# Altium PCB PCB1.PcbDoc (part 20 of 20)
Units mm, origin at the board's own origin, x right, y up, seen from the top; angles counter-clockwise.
Board outline 294.51 x 138.18 mm, 12 copper layers (Top Layer 1 _Signal, L2_GND, L3_Signals, L4_GND, L5_POWER, L6_Signals, L7_GND, L8_Signals, L9_GND, L10_POWER, L11_GND, Bottom Layer_Signals), stack 1.788 mm thick; 1254 components, 836 nets, 5699 pads, 2073 vias.
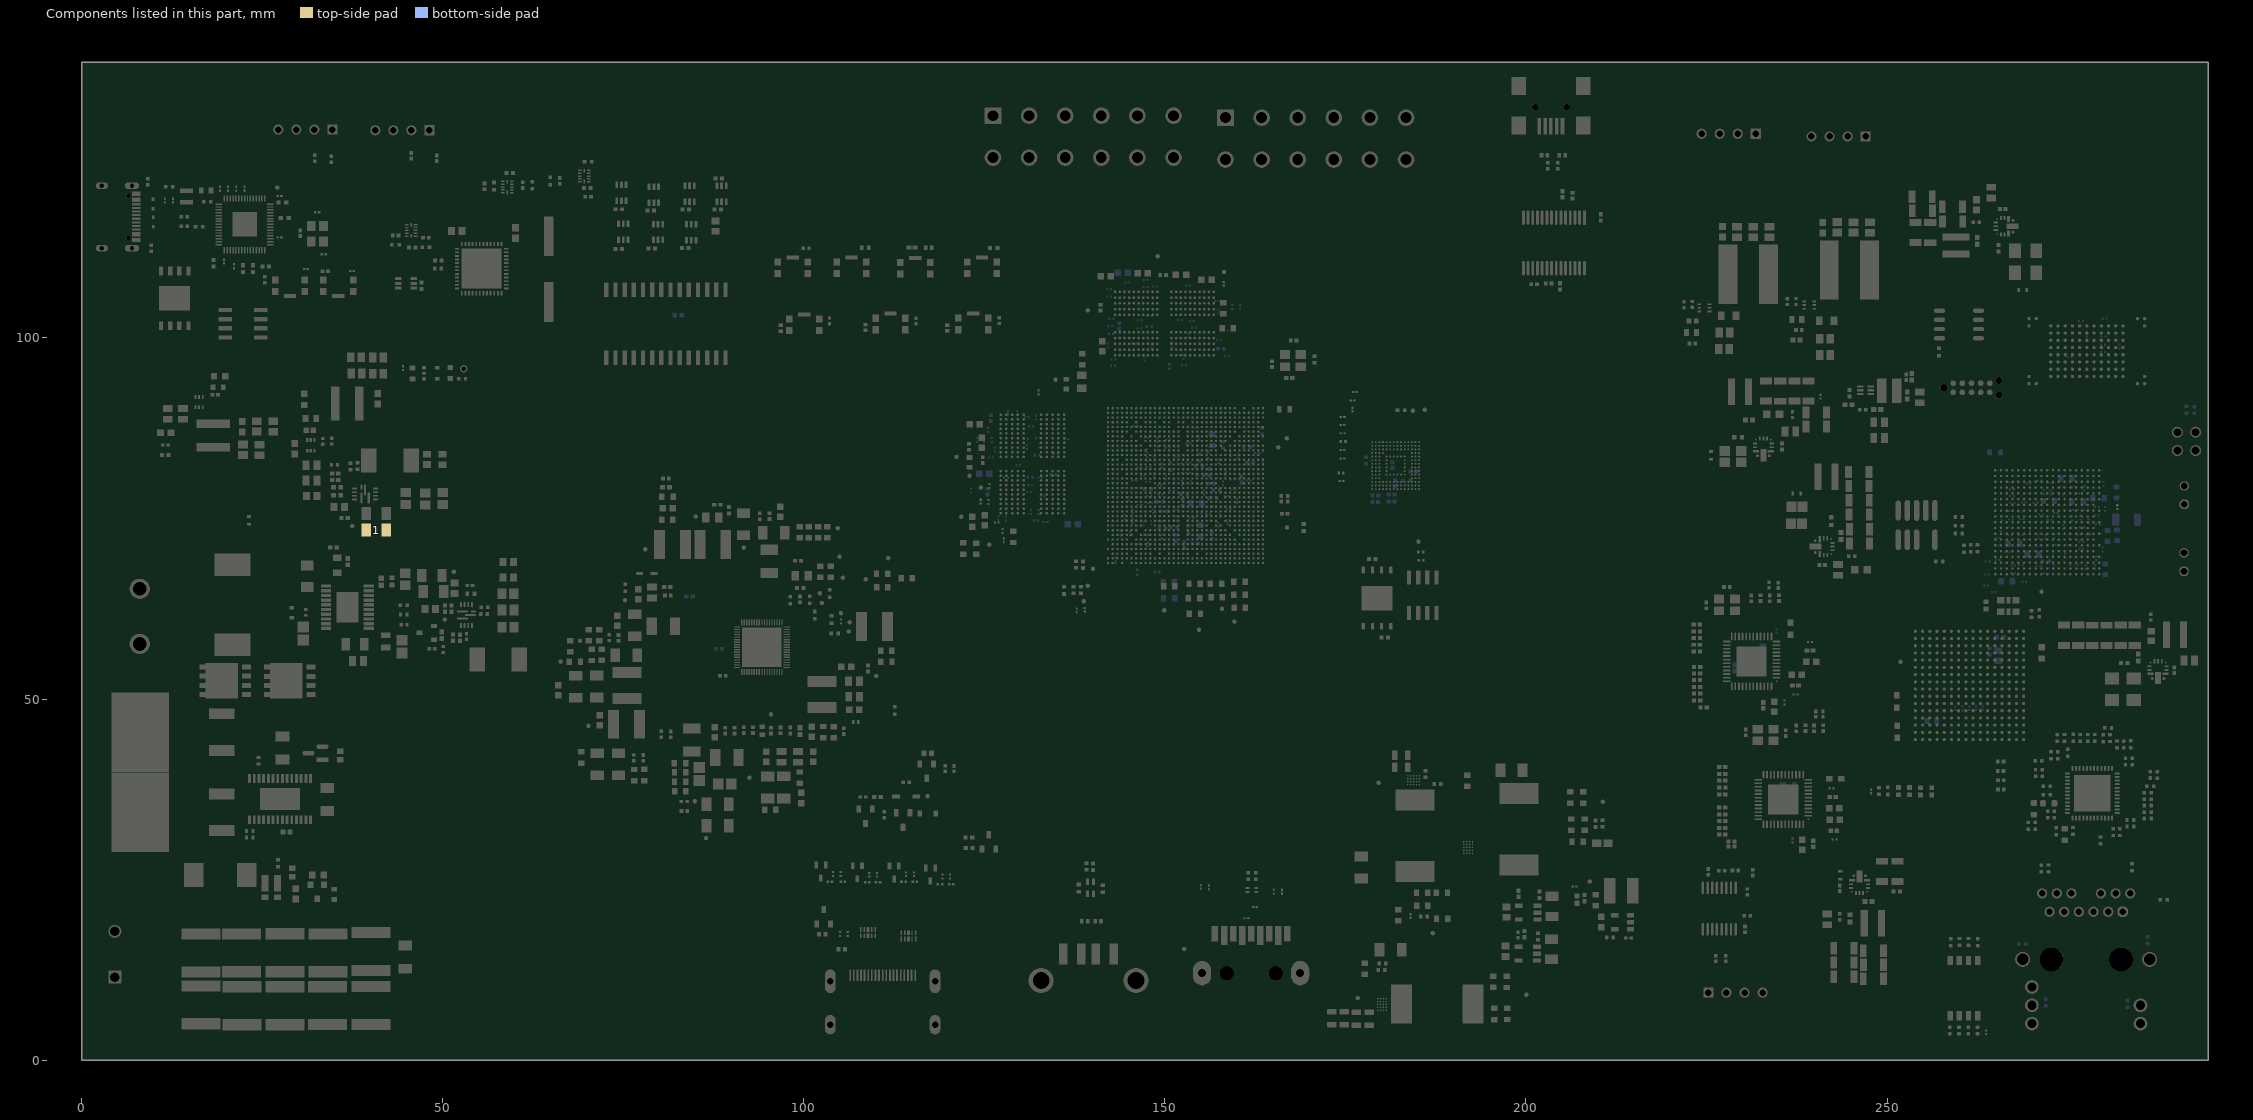
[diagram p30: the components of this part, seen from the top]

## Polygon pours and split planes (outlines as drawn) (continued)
NetC206_1 on Top Layer 1 _Signal "NONET_L04_P-001" (solid, pour order 236): 31.348,85.722 31.42,85.794 31.42,90.857 30.227,90.857 30.166,90.797 30.202,90.761 30.202,87.361 30.902,86.662 30.902,85.758
5V on Top Layer 1 _Signal "NONET_L04_P-001" (solid, pour order 235): 40.84,97.853 40.897,97.796 40.897,93.411 41.561,92.747 41.524,92.709 41.524,91.788 39.863,91.788 38.8,90.725 37.793,90.725 37.793,94.142 38.154,94.503 38.154,97.844
NetC436_1 on Top Layer 1 _Signal "NONET_L04_P-001" (solid, pour order 234): 39.424,78.502 39.431,78.509 39.431,81.181 40.533,81.181 40.91,81.559 40.91,83.091 39.678,83.091 38.8,82.213 37.822,82.213 37.822,81.282 39.085,80.019 39.085,78.502
NetR76_1 on Top Layer 1 _Signal "NONET_L04_P-001" (solid, pour order 233): 38.047,77.925 35.717,77.925 35.717,79.531 35.826,79.64 35.829,79.637 36.248,79.637 36.248,78.899 36.797,78.35 38.047,78.35
12V on Top Layer 1 _Signal "NONET_L04_P-001" (solid, pour order 226): 50.359,68 50.393,67.966 50.393,63.589 49.418,63.589 49.418,61.751 48.238,61.751 48.238,64.435 48.204,64.469 48.204,68.026
NetD13_2 on Top Layer 1 _Signal "NONET_L04_P-001" (solid, pour order 230): 13.584,31.72 18.505,31.72 18.774,31.45 18.774,21.542 13.854,21.542 13.764,21.632
NetQ18_1 on Top Layer 1 _Signal "NONET_L04_P-001" (solid, pour order 8): 31.112,53.515 34.977,53.515 34.977,49.678 31.006,49.678 31.006,53.41
3V3 on Top Layer 1 _Signal "NONET_L04_P-001" (solid, pour order 212): 69.229,121.732 69.223,121.726 67.559,121.726 67.269,121.436 64.665,121.436 64.665,121.157 64.665,120.972 67.744,120.972 68.237,121.465 69.246,121.465
3V3 on Top Layer 1 _Signal "NONET_L04_P-001" (solid, pour order 210): 19.432,115.828 19.429,115.824 16.548,115.824 16.548,115.171 19.424,115.171
3V3 on Top Layer 1 _Signal "NONET_L04_P-001" (solid, pour order 211): 20.248,118.88 20.282,118.913 20.282,120.045 22.702,120.045 22.904,120.247 22.893,120.258 22.893,120.626 19.021,120.626 19.021,119.366 19.391,118.88
RP_1V1 on Top Layer 1 _Signal "NONET_L04_P-001" (solid, pour order 214): 21.936,112.59 21.936,110.698 21.235,109.997 20.987,109.997 20.987,110.738 21.669,111.42 21.669,112.59
3V3 on Top Layer 1 _Signal "NONET_L04_P-001" (solid, pour order 213): 19.869,112.59 19.873,112.586 19.873,110.606 18.945,110.606 18.919,110.632 18.919,112.59
2V5_VSC on Top Layer 1 _Signal "NONET_L04_P-001" (solid, pour order 223): 261.779,35.623 260.256,37.145 247.439,37.145 247.439,35.623
3V3 on Top Layer 1 _Signal "NONET_L04_P-001" (solid, pour order 205): 27.339,119.866 27.4,119.805 27.4,118.476 25.832,118.476 25.832,119.866
NetR85_2 on Top Layer 1 _Signal "NONET_L04_P-001" (solid, pour order 221): 52.106,58.641 52.132,58.667 53.606,58.667 54.343,59.404 54.343,60.402 53.968,60.402 53.898,60.332 53.898,59.447 53.82,59.369 53.807,59.382 52.119,59.382
EN_MP on Top Layer 1 _Signal "NONET_L04_P-001" (solid, pour order 220): 52.7,62.852 52.598,62.75 50.048,62.75 50.048,63.245 49.985,63.307 50.644,63.307 50.794,63.457 50.786,63.464 50.786,64.712 50.951,64.877 52.457,64.877 52.716,64.618 52.716,62.845
NetC586_1 on Top Layer 1 _Signal "NONET_L04_P-001" (solid, pour order 218): 24 vertices, not listed, extent 21.582,22.115 29.454,33.911
NetC643_1 on Top Layer 1 _Signal "NONET_L04_P-001" (solid, pour order 216): 58.603,121.65 57.541,121.65 57.237,121.346 55.479,121.346 55.479,121.672 55.743,121.936 58.603,121.936
NetC542_1 on Top Layer 1 _Signal "NONET_L04_P-001" (solid, pour order 208): 19.432,118.428 17.601,118.428 17.601,120.819 17.663,120.881 18.295,120.881 18.295,119.057 18.612,118.74 19.432,118.74
+24V on Top Layer 1 _Signal "NONET_L04_P-001" (solid, pour order 204): 7.964,13.324 46.171,13.324 46.171,7.715 7.736,7.715
VCCA_1V8 on Top Layer 1 _Signal "NONET_L04_P-001" (solid, pour order 200): 45.881,112.3 47.316,112.3 47.316,114.02 47.107,114.229 45.911,114.229
VCC_5V0 on Top Layer 1 _Signal "NONET_L04_P-001" (solid, pour order 195): 40.349,78.327 50.918,78.327 50.918,82.586 45.003,82.586 42.851,80.433 42.851,79.495 42.2,78.845 40.349,78.845
VCC_1V8_S0 on Top Layer 1 _Signal "NONET_L04_P-001" (solid, pour order 26): 93.631,52.051 93.631,49.636 93.27,49.275 91.343,49.275 90.748,48.68 90.748,45.726 89.913,45.726 89.785,45.855 89.826,45.896 89.826,49.748 90.007,49.929 93.262,49.929 93.355,50.022 93.355,54.126 93.579,54.126
NetC445_1 on Top Layer 1 _Signal "NONET_L04_P-001" (solid, pour order 193): 55.521,61.956 55.521,53.9 53.798,53.9 53.733,53.965 53.733,58.469 54.757,59.493 54.757,61.013 53.709,61.013 53.709,61.851 54.691,61.851 54.927,62.087 55.505,62.087
LM_FB on Top Layer 1 _Signal "NONET_L04_P-001" (solid, pour order 32): 35.001,71.261 34.794,71.054 34.794,69.975 34.799,69.97 34.799,69.183 36.398,69.183 36.62,69.405 37.457,69.405 37.457,70.172 37.22,70.409 35.833,70.409 35.641,70.6 35.641,71.291 35.646,71.286
NetL19_1 on Top Layer 1 _Signal "NONET_L04_P-001" (solid, pour order 124): 192.073,29.176 201.522,29.176 201.858,28.839 201.858,26.599 192.969,26.599 192.047,27.522
VCC1 on Top Layer 1 _Signal "NONET_L04_P-001" (solid, pour order 117): 184.123,38.918 184.122,38.918 184.122,43.057 183.095,43.057 182.966,42.928 182.966,39.002 183.087,38.882 184.122,38.882
NetL21_1 on Top Layer 1 _Signal "NONET_L04_P-001" (solid, pour order 118): 184.145,38.706 184.157,38.695 184.157,37.674 186.053,37.674 186.098,37.629 186.098,34.469 182.765,34.469 182.72,34.514 182.799,34.593 182.799,38.729
PMIC_SW3 on Top Layer 1 _Signal "NONET_L04_P-001" (solid, pour order 18): 92.601,54.11 92.601,51.735 88.204,51.735 86.125,49.656 86.125,45.183 83.355,45.183 83.065,45.472 83.065,48.129 87.459,52.523 92.321,52.523 92.321,54.139
VDDA_1V2_S0 on Top Layer 1 _Signal "NONET_L04_P-001" (solid, pour order 25): 93.244,54.122 93.253,54.113 93.224,50.058 89.529,50.048 89.529,45.679 88.902,45.679 88.748,45.833 88.748,50.735 93.046,50.735 93.046,54.094 93.067,54.115
PMIC_PWR_CTRL2 on Top Layer 1 _Signal "NONET_L04_P-001" (solid, pour order 30): 94.681,54.04 94.681,46.558 94.721,46.519 94.623,46.421 94.623,45.699 93.745,45.699 93.53,45.914 93.53,47.683 93.762,47.916 94.373,47.916 94.373,54.017
VCC1 on Top Layer 1 _Signal "NONET_L04_P-001" (solid, pour order 34): 95.692,53.927 95.692,51.764 96.311,51.146 96.311,50.728 95.923,50.728 95.499,51.152 95.499,53.927
PMIC_FB9 on Top Layer 1 _Signal "NONET_L04_P-001" (solid, pour order 35): 96.222,54.042 96.222,52.172 97.395,50.999 97.395,46.004 97.817,45.582 99.937,45.582 99.937,46.706 98.288,48.355 98.288,50.788 96.36,52.717 96.36,54.011
PMIC_SW9 on Top Layer 1 _Signal "NONET_L04_P-001" (solid, pour order 37): 96.873,53.998 103.266,53.998 104.634,52.63 104.634,51.629 104.621,51.616 104.596,51.641 98.484,51.641 96.854,53.271 96.854,54.061 96.873,54.042
VCC1 on Top Layer 1 _Signal "NONET_L04_P-001" (solid, pour order 42): 97.397,56.394 97.44,56.352 102.477,56.352 103.19,57.064 103.173,57.081 99.95,57.081 99.501,56.632 97.338,56.632
NLDO4 on Top Layer 1 _Signal "NONET_L04_P-001" (solid, pour order 45): 97.387,57.41 97.502,57.295 99.011,57.295 101.483,59.767 104.193,59.767 104.19,61.083 102.257,61.083 98.794,57.62 97.39,57.62
NLDO3 on Top Layer 1 _Signal "NONET_L04_P-001" (solid, pour order 47): 97.243,57.718 98.808,57.718 101.933,60.842 101.933,61.394 101.043,61.394 101.043,60.754 98.323,58.034 97.249,58.034
VCC_2V0_PLDO_S3 on Top Layer 1 _Signal "NONET_L04_P-001" (solid, pour order 52): 97.369,58.385 98.176,58.385 100.221,60.431 100.221,63.706 99.091,63.706 99.091,62.823 99.091,59.632 98.139,58.681 97.375,58.681
NLDO1 on Top Layer 1 _Signal "NONET_L04_P-001" (solid, pour order 53): 97.237,58.751 98.194,58.751 99.003,59.561 99.003,63.334 98.858,63.48 97.789,63.48 97.789,62.946 98.647,62.087 98.647,59.598 98.108,59.059 97.237,59.059
PMIC_SPI_CS on Top Layer 1 _Signal "NONET_L04_P-001" (solid, pour order 54): 97.097,60.194 97.097,62.122 97.421,62.445 97.421,63.983 96.855,63.983 96.855,60.183
PMIC_SPI_CLK on Top Layer 1 _Signal "NONET_L04_P-001" (solid, pour order 55): 97.255,59.853 97.286,59.884 98.074,59.884 98.074,61.909 97.995,61.988 97.986,61.979 97.232,61.979
PMIC_INT_L on Top Layer 1 _Signal "NONET_L04_P-001" (solid, pour order 56): 96.758,60.413 96.758,64.035 97.809,65.086 99.414,65.086 99.414,65.774 97.661,65.774 96.506,64.604 96.506,60.413
VCC_1V8_S3_PLDO6 on Top Layer 1 _Signal "NONET_L04_P-001" (solid, pour order 57): 96.429,60.354 96.429,64.648 98.117,66.336 99.334,66.336 99.334,67.816 97.993,67.816 96.169,65.992 96.169,60.28 96.356,60.28
PMIC_SW4 on Top Layer 1 _Signal "NONET_L04_P-001" (solid, pour order 59): 95.414,60.472 95.414,65.721 96.574,66.882 96.574,68.168 93.866,68.168 93.911,68.122 93.911,64.993 95.049,63.855 95.049,60.418
VCCQ on Top Layer 1 _Signal "NONET_L04_P-001" (solid, pour order 61): 94.608,60.38 94.608,62.905 93.18,64.333 93.18,66.502 90.161,69.521 90.161,75.954 87.572,75.954 87.572,69.07 88.249,68.393 92.76,63.882 94.436,62.206 94.436,60.262
NetC162_1 on Top Layer 1 _Signal "NONET_L04_P-001" (solid, pour order 63): 95.479,75.426 93.305,75.426 92.491,74.613 90.534,74.613 90.534,76.532 90.572,76.57 95.491,76.57 95.491,75.846 95.504,75.833
NetC162_1 on Top Layer 1 _Signal "NONET_L04_P-001" (solid, pour order 64): 94.077,69.926 94.077,70.064 94.077,71.361 95.66,71.361 96.681,72.382 96.681,74.332 105.053,74.332 105.053,73.265 98.348,73.265 98.348,69.926
PMIC_SW10 on Top Layer 1 _Signal "NONET_L04_P-001" (solid, pour order 65): 94.293,60.289 94.352,60.289 94.352,62.12 87.008,69.464 87.008,73.867 86.727,73.894 84.755,73.894 84.755,69.213 89.598,64.37 91.31,64.37 94.122,61.558 94.122,60.289
PMIC_SW6 on Top Layer 1 _Signal "NONET_L04_P-001" (solid, pour order 67): 93.233,60.27 93.254,60.291 93.254,61.517 90.493,64.279 89.603,64.279 84.573,69.309 84.573,73.389 84.365,73.598 82.735,73.598 82.735,69.228 88.317,63.646 90.419,63.646 93.063,61.002 93.063,60.27
VOUT6 on Top Layer 1 _Signal "NONET_L04_P-001" (solid, pour order 69): 92.904,60.238 92.904,61.157 90.398,63.663 88.161,63.663 82.216,69.609 82.216,73.649 79.147,73.649 79.147,69.292 85.499,62.941 90.684,62.941 92.669,60.956 92.669,60.238
PMIC_VDC on Top Layer 1 _Signal "NONET_L04_P-001" (solid, pour order 70): 92.273,60.194 92.273,61.225 90.67,62.829 85.504,62.829 82.104,66.23 81.324,66.23 81.204,66.203 81.204,65.976 81.204,63.979 82.782,63.979 84.567,62.194 90.857,62.194 91.988,61.063 92.002,60.194
PMIC_SW2 on Top Layer 1 _Signal "NONET_L04_P-001" (solid, pour order 72): 81.407,61.248 83.28,61.248 84.379,60.149 91.201,60.149 91.285,60.065 91.285,59.511 81.481,59.511 81.439,59.553
RESET_L on Top Layer 1 _Signal "NONET_L04_P-001" (solid, pour order 75): 91.15,58.12 91.181,58.15 91.181,58.32 87.209,58.32 87.112,58.222 87.123,58.211 87.123,58.031 91.103,58.031 91.186,58.114
VCC1 on Top Layer 1 _Signal "NONET_L04_P-001" (solid, pour order 78): 91.175,57.249 91.171,57.252 88.595,57.252 88.097,56.754 88.108,56.743 91.168,56.743
PMIC_SW5 on Top Layer 1 _Signal "NONET_L04_P-001" (solid, pour order 79): 91.102,56.638 87.911,56.638 80.19,48.917 76.442,48.917 76.442,44.661 76.63,44.473 78.182,44.473 78.182,47.058 79.215,47.058 88.475,56.318 91.102,56.318
VDD_GPIO_S0 on Top Layer 1 _Signal "NONET_L04_P-001" (solid, pour order 82): 91.099,55.316 88.882,55.316 79.937,46.371 79.937,45.317 80.215,45.039 82.907,45.039 82.907,48.288 89.505,54.885 91.111,54.885
PMIC_SW1 on Top Layer 1 _Signal "NONET_L04_P-001" (solid, pour order 83): 91.15,54.792 91.147,54.789 89.35,54.789 89.35,53.582 91.186,53.582
PMIC_SW1 on Top Layer 1 _Signal "NONET_L04_P-001" (solid, pour order 86): 91.645,43.073 91.639,43.079 91.639,44.131 89.193,44.131 89.087,44.026 89.146,43.967 89.146,40.673 91.634,40.673 91.639,40.679
NetC41_1 on Top Layer 1 _Signal "NONET_L04_P-001" (solid, pour order 87): 88.508,43.1 88.497,43.089 88.497,39.91 89.047,39.36 89.047,37.369 87.089,37.369 86.671,37.787 86.671,39.6 84.737,39.6 84.405,39.932 84.405,41.593 86.353,41.593 86.902,42.142 86.902,43.111
NetC76_1 on Top Layer 1 _Signal "NONET_L04_P-001" (solid, pour order 88): 17 vertices, not listed, extent 82.868,31.486 87.393,43.417
NetC61_1 on Top Layer 1 _Signal "NONET_L04_P-001" (solid, pour order 89): 75.615,62.821 79.559,62.821 79.559,59.021 79.446,58.907 78.257,58.907 78.257,60.437 78.03,60.663 75.643,60.663
NetC61_1 on Top Layer 1 _Signal "NONET_L04_P-001" (solid, pour order 91): 74.648,55.089 74.648,58.276 74.567,58.357 72.375,58.357 72.253,58.479 72.221,58.446 69.721,58.446 69.721,56.545 69.883,56.383 72.682,56.383 73.095,55.97 73.095,55.072
VCC_2V0_PLD0_S3 on Top Layer 1 _Signal "NONET_L04_P-001" (solid, pour order 94): 65.238,51.128 72.66,51.128 72.835,50.954 72.835,48.999 65.284,48.999 65.183,49.1
VCC1 on Top Layer 1 _Signal "NONET_L04_P-001" (solid, pour order 121): 179.955,7.392 179.927,7.365 172.327,7.365 172.327,6.08 179.932,6.08 179.945,6.067
NetL20_1 on Top Layer 1 _Signal "NONET_L04_P-001" (solid, pour order 122): 180.149,7.417 183.992,7.417 183.992,6.073 180.121,6.073
VCC3V3_LCD on Top Layer 1 _Signal "NONET_L04_P-001" (solid, pour order 129): 204.364,19.195 204.343,19.216 200.98,19.216 200.98,19.74 201.116,19.876 201.127,19.865 204.375,19.865
P28.LED1 on Top Layer 1 _Signal "NONET_L04_P-001" (solid, pour order 186): 281.625,36.892 282.878,36.892 286.211,40.225 286.752,40.225 286.703,40.176 286.703,38.881 285.995,38.881 283.627,36.513 281.602,36.513
P28.LED2 on Top Layer 1 _Signal "NONET_L04_P-001" (solid, pour order 185): 281.561,35.87 283.505,35.87 285.713,38.079 285.997,38.079 285.997,36.935 285.785,36.723 285.508,36.723 284.317,35.532 281.561,35.532
PHYAD2 on Top Layer 1 _Signal "NONET_L04_P-001" (solid, pour order 183): 281.609,34.992 285.837,34.992 285.837,36.4 285.435,36.4 284.468,35.432 281.609,35.432
NetC19_2 on Top Layer 1 _Signal "NONET_L04_P-001" (solid, pour order 180): 15.903,91.582 15.922,91.601 15.922,93.082 17.695,93.082 17.695,91.823 18.474,91.823 18.474,92.479 18.853,92.858 18.853,95.417 17.766,95.417 17.628,95.278 17.628,93.553 15.29,93.553 15.29,91.588
NetL14_1 on Top Layer 1 _Signal "NONET_L04_P-001" (solid, pour order 179): 16.448,90.729 16.448,89.924 20.305,89.924 21.078,89.151 21.046,89.12 21.046,87.409 16.053,87.409 16.053,90.681 16.108,90.737
12V on Top Layer 1 _Signal "NONET_L04_P-001" (solid, pour order 177): 15.958,89.727 15.951,89.719 11.194,89.719 11.194,87.645 11.502,87.337 11.502,84.726 10.303,84.726 9.98,85.05 9.98,91.06 10.027,91.107 15.966,91.107
NetL27_1 on Top Layer 1 _Signal "NONET_L04_P-001" (solid, pour order 173): 239.631,104.319 243.509,104.319 243.509,111.426 243.128,111.807 240.402,111.807 240.402,104.931 240.278,104.806 239.631,104.806
NetC678_2 on Top Layer 1 _Signal "NONET_L04_P-001" (solid, pour order 172): 224.361,103.888 224.361,99.131 223.944,98.714 223.173,98.714 223.173,103.594 223.466,103.888
5V on Top Layer 1 _Signal "NONET_L04_P-001" (solid, pour order 168): 225.364,103.843 225.442,103.765 227.65,103.765 227.65,98.109 226.971,97.43 225.364,97.43 225.364,103.034 224.985,103.412 224.985,103.413 224.985,103.85
3V3 on Top Layer 1 _Signal "3V3_L01_P162" (solid, pour order 162): 15.88,84.244 15.938,84.302 21.22,84.302 21.568,84.65 26.502,84.65 27.373,85.521 27.373,87.398 27.218,87.552 21.858,87.552 19.846,85.54 15.88,85.54
5V on Top Layer 1 _Signal "NONET_L04_P-001" (solid, pour order 151): 240.858,70.504 240.84,70.486 240.84,69.468 239.716,68.344 238.689,68.344 238.689,68.915 238.893,69.119 240.026,69.119 240.508,69.602 240.508,70.504
1V0_VSC on Top Layer 1 _Signal "1V0_VSC_L01_P165" (solid, pour order 165): 265.294,115.14 265.29,115.137 259.98,115.137 259.98,114.631 260.665,113.945 263.595,113.945 264.407,114.757 265.303,114.757
1V0_VSC on Top Layer 1 _Signal "1V0_VSC_L01_P164" (solid, pour order 164): 262.817,113.555 262.763,113.502 257.58,113.502 257.58,114.755 256.97,115.365 253.061,115.365 252.9,115.526 252.9,116.575 254.624,116.575 255.61,117.56 255.61,120.484 256.938,120.484 258.33,119.092 258.33,115.087 262.817,115.087
12V on Top Layer 1 _Signal "12V_L01_P163" (solid, pour order 163): 266.052,114.57 266.037,114.555 266.037,106.349 266.084,106.301 268.522,106.301 268.522,112.588 267.023,114.086 267.023,114.555
NetC186_2 on Top Layer 1 _Signal "NONET_L04_P-001" (solid, pour order 160): 18 vertices, not listed, extent 245.851,17.088 254.762,31.254
12V on Top Layer 1 _Signal "NONET_L04_P-001" (solid, pour order 159): 246.79,25.168 252.302,25.168 252.302,24.175 252.287,24.16 252.25,24.197 246.778,24.197
12V on Top Layer 1 _Signal "NONET_L04_P-001" (solid, pour order 158): 245.474,25.049 244.615,25.049 244.416,25.249 242.279,25.249 241.733,25.249 241.733,24.7 244.396,24.7 245.494,24.7
NetC186_2 on Top Layer 1 _Signal "NONET_L04_P-001" (solid, pour order 157): 246.533,28.672 246.548,24.537 246.123,24.112 243.202,24.112 243.202,24.523 245.66,24.523 245.861,24.724 245.861,28.672
1V1 on Top Layer 1 _Signal "NONET_L04_P-001" (solid, pour order 156): 246.852,23.468 246.842,23.458 246.842,11.571 246.571,11.299 244.921,11.299 244.921,18.064 244.503,18.482 244.503,19.427 244.573,19.497 245.548,19.497 245.548,19.975 246.513,20.94 246.513,23.363
NetC602_2 on Top Layer 1 _Signal "NONET_L04_P-001" (solid, pour order 155): 241,81.577 240.973,81.55 236.017,81.55 235.245,80.779 235.245,79.716 240.972,79.716 241.002,79.747
NetC195_2 on Top Layer 1 _Signal "NONET_L04_P-001" (solid, pour order 143): 229.612,88.651 229.612,95.253 227.087,95.253 227.087,88.651
NetC195_2 on Top Layer 1 _Signal "NONET_L04_P-001" (solid, pour order 140): 233.291,83.583 233.291,84.612 233.388,84.709 234.459,84.709 234.459,84.999 234.495,85.035 234.424,85.106 232.485,85.106 232.391,85.012 232.391,80.522 233.291,80.522
SW_LM on Top Layer 1 _Signal "NONET_L04_P-001" (solid, pour order 11): 17 vertices, not listed, extent 18.225,49.932 31.679,59.299
HB_LM on Top Layer 1 _Signal "NONET_L04_P-001" (solid, pour order 9): 29.858,60.803 29.879,60.824 32.033,60.824 32.541,61.332 34.652,61.332 34.652,60.857 34.566,60.771 32.589,60.771 31.718,59.9 31.718,59.104 29.858,59.104 29.826,59.136
SW_LM on Top Layer 1 _Signal "NONET_L04_P-001" (solid, pour order 10): 34.593,60.017 34.593,59.317 32.551,57.276 29.815,57.276 29.794,57.297 29.794,58.868 29.949,59.023 33.166,59.023 33.166,60.05 34.55,60.05 34.556,60.055
NetR294_1 on Top Layer 1 _Signal "NONET_L04_P-001" (solid, pour order 7): 39.111,60.653 42.297,60.653 43.972,58.978 45.107,58.978 45.107,57.671 45.107,57.357 43.745,57.357 42.774,58.328 41.576,58.328 41.381,58.524 41.381,59.854 41.115,60.121 39.111,60.121
GND on Bottom Layer_Signals "NONET_L04_P-001" (solid, pour order 356): 147.063,86.876 160.986,86.876 160.986,73.594 157.88,70.488 156.477,71.891 146.854,71.891 146.854,86.6 146.867,86.614
0V9 on Bottom Layer_Signals "NONET_L04_P-001" (solid, pour order 202): 24 vertices, not listed, extent 268.117,69.925 277.573,77.919
NetC195_2 on Bottom Layer_Signals "NONET_L04_P-001" (solid, pour order 141): 233.272,82.714 229.662,82.714 229.662,96.414 227.1,96.414 227.1,82.902 229.471,80.531 233.272,80.531
VDD_LOG_S0 on Bottom Layer_Signals "NONET_L04_P-001" (solid, pour order 369): 86.955,49.49 87.015,49.549 88.508,49.549 88.508,45.398 84.536,41.427 84.536,31.154 82.117,31.154 81.341,31.931 81.341,43.786 85.79,48.235 85.79,49.549
0V9 on Bottom Layer_Signals "NONET_L04_P-001" (solid, pour order 348): 282.979,75.482 283.086,75.589 287.858,75.589 287.858,66.412 289.25,65.02 289.204,64.974 289.204,63.276 285.931,63.276 285.946,63.292 285.946,72.836 285.472,73.31 282.948,73.31
2V5_DP on Bottom Layer_Signals "NONET_L04_P-001" (solid, pour order 339): 237.684,101.286 237.372,100.974 237.372,98.432 237.595,98.209 245.057,98.209 245.92,99.071 245.92,104.765 245.756,104.928 246.053,105.226 248.595,105.226 248.595,99.547 245.474,96.425 236.435,96.425 236.049,96.812 236.049,101.346
NetC511_1 on Bottom Layer_Signals "NONET_L04_P-001" (solid, pour order 329): 187.43,27.735 188.666,28.972 188.666,38.377 188.169,38.874 187.534,38.874 187.534,32.658 183.767,28.891 183.767,27.793
PMIC_SW1 on Bottom Layer_Signals "NONET_L04_P-001" (solid, pour order 85): 91.255,54.772 91.444,40.67 89.12,40.649 89.12,54.435 89.495,54.81
VCC1 on Bottom Layer_Signals "NONET_L04_P-001" (solid, pour order 311): 90.992,60.487 90.983,60.496 90.983,61.555 95.926,61.555 96.108,61.737 96.108,63.426 89.77,63.426 89.047,62.702 89.047,60.544
VCC1 on Bottom Layer_Signals "NONET_L04_P-001" (solid, pour order 309): 102.851,56.934 102.864,56.921 102.864,54.264 101.561,54.264 101.491,54.333 101.497,54.34 101.497,56.833 101.611,56.946
+24V on Bottom Layer_Signals "NONET_L04_P-001" (solid, pour order 224): 12.963,8.109 12.963,59.303 3.469,59.303 3.396,59.376 3.177,59.157 3.177,27.024 8.07,22.131 8.07,8.474 8.439,8.104 12.863,8.104
NetC602_2 on Bottom Layer_Signals "NONET_L04_P-001" (solid, pour order 154): 239.406,71.532 239.147,71.532 236.693,71.532 236.693,79.041 236.855,79.203 241,79.203 241,81.577 236.043,81.577 235.27,80.803 235.27,71.413 236.034,70.648 236.043,70.658 239.406,70.658
VCC_1V8_S0 on L8_Signals "NONET_L04_P-001" (solid, pour order 307): 34 vertices, not listed, extent 89.687,39.701 159.434,86.25
PLDO4 on L8_Signals "NONET_L04_P-001" (solid, pour order 305): 20 vertices, not listed, extent 95.031,45.449 149.824,75.239
NLDO5 on L8_Signals "NONET_L04_P-001" (solid, pour order 306): 23 vertices, not listed, extent 100.752,54.126 148.779,75.58
1V2 on L8_Signals "NONET_L04_P-001" (solid, pour order 370): 33 vertices, not listed, extent 245.474,70.132 269.245,94.808
1V8 on L5_POWER "NONET_L04_P-001" (solid, pour order 188): 19 vertices, not listed, extent 271.687,94.653 278.629,102.654
VDD_CPU_BIG1_S0 on L5_POWER "NONET_L04_P-001" (solid, pour order 308): 18 vertices, not listed, extent 154.832,39.06 197.546,84.232
VDD_LOG_S0 on L5_POWER "NONET_L04_P-001" (solid, pour order 291): 23 vertices, not listed, extent 81.823,31.781 153.584,79.147
PLDO5 on L5_POWER "NONET_L04_P-001" (solid, pour order 303): 20 vertices, not listed, extent 96.345,46.219 149.355,77.949
12V on L5_POWER "NONET_L04_P-001" (solid, pour order 343): 252.498,28.184 231.917,15.866 184.04,15.866 182.212,14.038 182.11,14.14 62.304,14.14 28.879,47.565 28.879,80.817 22.334,80.817 22.334,37.61 55.155,4.788 245.651,4.788 251.817,9.833
VDD_VDENC_S0 on L5_POWER "NONET_L04_P-001" (solid, pour order 283): 19 vertices, not listed, extent 97.668,70.195 150.555,80.571
VCC1V8_PMU_DDR_S3 on L5_POWER "NONET_L04_P-001" (solid, pour order 253): 138.429,87.396 133.327,87.396 132.061,86.131 128.302,86.131 125.118,89.314 125.118,89.813 102.609,89.813 100.154,87.358 123.584,87.358 124.21,86.731 124.21,84.287 136.577,84.287 138.325,86.034
VCC1V8_PMU_DDR_S3 on L5_POWER "NONET_L04_P-001" (solid, pour order 251): 33 vertices, not listed, extent 99.789,77.304 158.813,113.278
VDDHS on L5_POWER "NONET_L04_P-001" (solid, pour order 371): 32 vertices, not listed, extent 271.403,68.413 281.108,78.778
NLDO3 on L5_POWER "NONET_L04_P-001" (solid, pour order 298): 147.02,77.109 148.045,77.109 148.045,73.666 143.136,68.756 129.253,68.756 129.253,69.867 129.94,70.554 141.909,70.554 146.865,75.51 146.865,77.061
VDD_CPU_BIG0_S0 on L5_POWER "NONET_L04_P-001" (solid, pour order 326): 30 vertices, not listed, extent 151.806,13.811 180.214,83.012
NetC35_1 on L5_POWER "NONET_L04_P-001" (solid, pour order 349): 20 vertices, not listed, extent 158.578,74.741 170.067,83.336
VCC1V8_PMU_DDR_S3 on L5_POWER "NONET_L04_P-001" (solid, pour order 252): 18 vertices, not listed, extent 156.8,81.267 160.971,109.575
VDDQ_DDR_CK on L5_POWER "NONET_L04_P-001" (solid, pour order 304): 148.377,83.877 148.377,85.144 147.615,87.811 146.061,89.365 146.061,89.43 141.815,93.676 138.577,93.676 136.674,95.579 136.273,95.506 135.883,94.879 138.325,92.437 141.084,92.437 145.161,88.36 146.777,86.744 146.777,83.835
VDD_NPU_S0 on L5_POWER "NONET_L04_P-001" (solid, pour order 323): 21 vertices, not listed, extent 154.849,23.684 178.496,77.483
VDD_LOG_S0 on L5_POWER "NONET_L04_P-001" (solid, pour order 293): 152.511,78.86 152.511,78.999 151.926,79.585 151.926,83.034 153.857,83.034 153.932,84.025 153.988,84.775 153.957,84.867 152.791,84.867 151.789,83.865 150.761,83.865 150.761,79.54 151.532,78.769 151.538,78.774 152.296,78.774
VDD_GPU_S0 on L5_POWER "NONET_L04_P-001" (solid, pour order 284): 151.372,77.161 151.372,60.987 144.122,53.737 127.069,53.737 107.856,34.525 94.163,34.525 93.6,35.087 93.6,37.539 102.083,37.539 122.879,58.336 144.365,58.336 149.398,63.369 149.398,77.165
VCC1V8_PMU_DDR_S3 on L5_POWER "NONET_L04_P-001" (solid, pour order 254): 136.467,76.357 99.923,76.954 99.923,81.141 121.604,81.141 122.812,79.933 122.841,79.962 129.35,79.962 129.633,80.245 136.467,80.245
VDD_GPU_S0 on L5_POWER "NONET_L04_P-001" (solid, pour order 264): 150.859,78.036 150.874,78.022 151.263,78.022 151.419,77.866 151.419,75.226 150.764,74.571 150.633,74.702 149.929,74.702 149.929,77.602 150.378,78.051
VCC1 on L3_Signals "NONET_L04_P-001" (solid, pour order 346): 90.526,56.857 103.115,56.857 103.157,56.899 103.678,56.378 103.678,41.809 93.507,41.809 90.631,44.685 90.631,55.898
VCC1 on L3_Signals "NONET_L04_P-001" (solid, pour order 344): 90.682,61.739 90.696,61.726 90.696,56.854 88.786,56.854 88.341,57.298 88.341,61.807
VCC1 on L3_Signals "NONET_L04_P-001" (solid, pour order 313): 89.059,61.908 91.576,61.908 92.287,61.197 92.287,52.516 90.854,52.516 90.83,52.492 90.702,52.621 90.702,58.074 88.861,59.915 88.861,61.512
NetD13_2 on L3_Signals "NONET_L04_P-001" (solid, pour order 229): 6.102,15.745 6.102,21.16 18.505,21.16 18.752,21.407 18.752,31.9 0.697,31.9 0.678,31.881 0.678,15.745
1V8 on L10_POWER "NONET_L04_P-001" (solid, pour order 366): 32 vertices, not listed, extent 228.372,2.275 290.245,101.81
VCCQ on L10_POWER "NONET_L04_P-001" (solid, pour order 335): 39 vertices, not listed, extent 62.34,29.434 181.694,84.536
EMMC_VCC on L10_POWER "NONET_L04_P-001" (solid, pour order 317): 29 vertices, not listed, extent 111.961,13.426 199.721,86.65
NLDO2 on L10_POWER "NONET_L04_P-001" (solid, pour order 300): 17 vertices, not listed, extent 108.851,68.384 151.905,83.517
VDDQ_DRAM on L10_POWER "NONET_L04_P-001" (solid, pour order 256): 24 vertices, not listed, extent 122.036,72.164 160.14,109.821
VDD_CPU_LIT_S0 on L10_POWER "NONET_L04_P-001" (solid, pour order 267): 156,80.356 156,79.789 154.885,78.675 154.886,67.974 148.036,61.124 86.953,61.124 84.661,58.832 84.661,57.481 79.064,57.481 79.064,62.925 80.97,64.831 148.164,64.831 153.337,70.004 153.337,79.055 154.643,80.361
VDD_DDR_S0 on L10_POWER "NONET_L04_P-001" (solid, pour order 295): 27 vertices, not listed, extent 68.74,41.973 153.251,84.473
VDD_DDR_S0 on L10_POWER "NONET_L04_P-001" (solid, pour order 279): 149.432,84.233 152.419,84.233 152.419,83.689 150.732,83.689 150.475,83.432 150.475,81.452 150.274,81.252 149.322,81.252 149.322,81.886 149.865,82.429 149.865,83.566 149.432,84
1V2 on L10_POWER "NONET_L04_P-001" (solid, pour order 368): 25 vertices, not listed, extent 250.482,70.065 269.03,94.683
VOUT6 on L6_Signals "NONET_L04_P-001" (solid, pour order 258): 29 vertices, not listed, extent 121.375,71.292 160.132,109.424
VCCA_1V8 on L6_Signals "NONET_L04_P-001" (solid, pour order 281): 153.505,73.283 137.058,58.774 104.314,58.774 93.913,47.016 92.482,47.016 92.482,48.898 105.019,61.434 135.65,61.434 148.918,73.283
VOUT9 on L6_Signals "NONET_L04_P-001" (solid, pour order 347): 137.502,92.532 144.905,92.532 151.491,85.945 148.466,82.919 148.466,81.323 146.09,78.948 142.057,78.948 145.512,82.402 145.512,87.642 141.857,91.297 137.435,91.297
VOUT9 on L6_Signals "NONET_L04_P-001" (solid, pour order 337): 47 vertices, not listed, extent 139.062,67.14 155.783,87.755
VCCA_1V8 on L6_Signals "NONET_L04_P-001" (solid, pour order 280): 23 vertices, not listed, extent 148.834,72.283 159.27,85.498
NLDO4 on L6_Signals "NONET_L04_P-001" (solid, pour order 334): 150.514,72.102 150.514,73.171 149.516,74.169 146.626,74.169 140.803,68.347 126.131,68.347 124.547,66.763 124.547,65.334 127.525,65.334 128.937,66.746 141.762,66.746 148.163,73.147 149.157,73.147 149.516,72.788 149.516,72.102
GND on L2_GND "NONET_L04_P-001" (solid, pour order 350): 0.86,138.23 0.632,138.002 0,0 293.181,-0.178 294.777,1.418 294.777,137.774
GND on L4_GND "NONET_L04_P-001" (solid, pour order 351): 0.75,138.331 0.522,138.103 0,0 293.329,0.181 294.667,1.519 294.667,137.875
GND on L7_GND "NONET_L04_P-001" (solid, pour order 352): 0.843,138.354 0.615,138.126 0,0 293.164,-0.053 294.76,1.543 294.76,137.898
GND on L9_GND "NONET_L04_P-001" (solid, pour order 353): 0.124,138.17 0.052,0.022 293.108,0.023 294.267,1.181 294.538,138.17
GND on L11_GND "NONET_L04_P-001" (solid, pour order 354): 0.501,138.159 0.273,137.931 0,0 292.821,-0.248 294.418,1.348 294.418,137.703

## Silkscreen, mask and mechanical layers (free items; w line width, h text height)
Mechanical 15:
  lines w0.003: 132.168,124.948 132.169,124.947

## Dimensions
294.1,137.903 to 294.513,0 on Top Component Center
0.34,138.587 to 294.795,138.355 on Top Component Center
